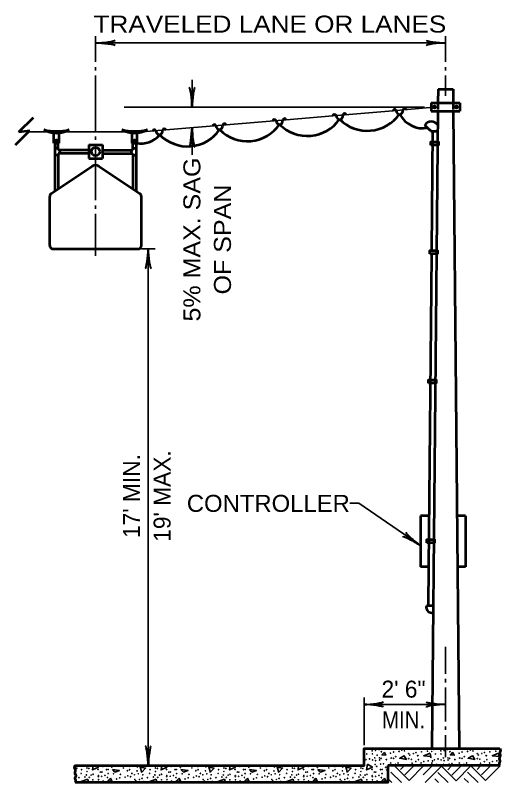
# Model space of a CAD drawing. Extents: x -1 to 679, y 1 to 441.
# Drawn here: x 376.2 to 447.7, y 250 to 362.8 of the extents above; entities that cross this region are included whole.
import ezdxf
from ezdxf.enums import TextEntityAlignment as Align

# ---------------------------------------------------------------- set-up
doc = ezdxf.new("R2010")
doc.units = 0
doc.layers.add('1', color=7, linetype='Continuous', lineweight=35)

msp = doc.modelspace()

# ---------------------------------------------------------------- hatches: boundary and pattern name
at = {"layer": '1'}
for points in [[(438.098, 349.333, 1), (437.774, 349.333, 1)], [(441.34, 349.333, 1), (441.016, 349.333, 1)], [(382.431, 344.383, 1), (382.181, 344.383, 1)], [(393.932, 344.38, 1), (393.682, 344.38, 1)]]:
    msp.add_hatch(color=256, dxfattribs=at).paths.add_polyline_path(points)

# ---------------------------------------------------------------- linework, layer by layer
for p, q in [((388.058, 359.754), (388.058, 355.955)), ((439.572, 355.955), (439.572, 359.754)), ((388.058, 358.754), (439.572, 358.754)), ((388.058, 355.205), (388.058, 354.705)), ((439.572, 354.705), (439.572, 355.205)), ((388.058, 353.955), (388.058, 345.754)), ((402.26, 349.33), (402.26, 353.33)), ((439.572, 350.955), (439.572, 353.955)), ((392.26, 349.33), (436.451, 349.33)), ((422.964, 348.038), (431.812, 348.784)), ((431.812, 348.784), (437.781, 349.287)), ((416.115, 347.461), (422.967, 348.038)), ((398.421, 345.969), (407.267, 346.715)), ((407.267, 346.715), (416.115, 347.461)), ((381.185, 345.675), (378.165, 345.675)), ((392.685, 345.675), (383.431, 345.675)), ((394.93, 345.675), (398.421, 345.969)), ((402.26, 342.293), (402.26, 346.293)), ((388.058, 345.004), (388.058, 344.504)), ((388.058, 340.754), (388.058, 335.605)), ((388.058, 334.855), (388.058, 334.355)), ((388.058, 333.605), (388.058, 328.456)), ((388.058, 328.456), (388.058, 327.456)), ((394.808, 328.456), (396.808, 328.456)), ((395.808, 328.456), (395.808, 252.456)), ((439.572, 265.956), (439.572, 269.956)), ((439.572, 264.706), (439.572, 265.206)), ((439.572, 258.956), (439.572, 263.956)), ((427.572, 255.456), (427.572, 262.456)), ((427.572, 261.456), (439.572, 261.456)), ((439.572, 257.706), (439.572, 258.206)), ((439.572, 256.956), (439.572, 253.706)), ((430.859, 251.872), (431.072, 251.848)), ((431.072, 251.66), (430.859, 251.872)), ((432.052, 252.416), (434.192, 250.276)), ((433.472, 252.416), (432.952, 251.896)), ((434.912, 252.416), (433.592, 251.096)), ((436.332, 252.416), (434.192, 250.276)), ((437.612, 252.416), (436.292, 251.096)), ((439.032, 252.416), (436.572, 249.956)), ((438.108, 252.456), (438.139, 252.672)), ((438.179, 252.652), (438.523, 252.456)), ((438.932, 252.416), (441.132, 250.216)), ((440.452, 252.416), (439.892, 251.836)), ((441.892, 252.416), (440.512, 251.036)), ((443.312, 252.416), (441.132, 250.216)), ((443.312, 252.416), (445.452, 250.276)), ((444.732, 252.416), (444.212, 251.896)), ((446.172, 252.416), (444.852, 251.096)), ((447.592, 252.416), (445.452, 250.276)), ((431.072, 250.556), (431.672, 249.956)), ((431.532, 251.516), (433.092, 249.956)), ((438.452, 251.456), (439.968, 249.956)), ((442.332, 250.556), (442.932, 249.956)), ((442.792, 251.516), (444.352, 249.956)), ((393.159, 250.112), (392.873, 249.956)), ((393.233, 249.956), (393.119, 250.132)), ((403.239, 250.112), (402.953, 249.956)), ((403.313, 249.956), (403.199, 250.132)), ((413.319, 250.112), (413.033, 249.956)), ((413.393, 249.956), (413.279, 250.132)), ((423.399, 250.112), (423.113, 249.956)), ((423.473, 249.956), (423.359, 250.132)), ((437.992, 250.496), (438.532, 249.956))]:
    msp.add_line(p, q, dxfattribs=at)
at = {"layer": '1', "lineweight": 53}
for p, q in [((438.47, 351.955), (438.451, 349.955)), ((438.47, 351.955), (440.673, 351.955)), ((440.673, 351.955), (440.692, 349.955)), ((437.451, 349.955), (441.692, 349.955)), ((437.451, 349.955), (437.451, 348.705)), ((441.692, 349.955), (441.692, 348.705)), ((438.449, 349.705), (438.442, 348.955)), ((440.694, 349.705), (440.701, 348.955)), ((376.783, 345.687), (378.905, 347.809)), ((437.451, 348.705), (441.692, 348.705)), ((438.44, 348.705), (437.572, 254.956)), ((440.704, 348.705), (441.572, 254.956)), ((437.222, 345.964), (436.515, 346.671)), ((376.25, 343.761), (378.372, 345.882)), ((376.783, 345.687), (378.372, 345.882)), ((381.933, 344.004), (381.933, 345.504)), ((382.683, 344.004), (382.683, 345.504)), ((393.433, 344.004), (393.433, 345.504)), ((394.183, 344.004), (394.183, 345.504)), ((438.412, 345.705), (437.412, 345.705)), ((437.662, 345.705), (437.5, 328.213)), ((381.933, 344.004), (382.683, 344.004)), ((382.058, 344.004), (382.058, 336.956)), ((382.558, 343.254), (382.058, 343.254)), ((382.558, 343.004), (382.558, 344.004)), ((387.058, 343.754), (389.058, 343.754)), ((387.058, 343.754), (387.058, 341.754)), ((389.058, 343.754), (389.058, 341.754)), ((393.433, 344.004), (394.183, 344.004)), ((393.558, 343.004), (393.558, 344.004)), ((393.558, 343.254), (394.058, 343.254)), ((394.058, 344.004), (394.058, 336.956)), ((382.558, 342.254), (382.058, 342.254)), ((387.058, 343.004), (382.558, 343.004)), ((387.058, 342.504), (382.558, 342.504)), ((382.558, 342.504), (382.558, 337.289)), ((382.808, 343.004), (382.808, 342.504)), ((389.058, 343.004), (393.558, 343.004)), ((389.058, 342.504), (393.558, 342.504)), ((393.308, 343.004), (393.308, 342.504)), ((393.558, 342.504), (393.558, 337.289)), ((393.558, 342.254), (394.058, 342.254)), ((387.058, 341.754), (389.058, 341.754)), ((381.53, 336.604), (387.503, 340.586)), ((388.612, 340.586), (394.585, 336.604)), ((381.308, 328.956), (381.308, 336.188)), ((394.808, 328.956), (394.808, 336.188)), ((381.808, 328.456), (394.308, 328.456)), ((437.495, 327.706), (437.069, 281.714)), ((435.889, 289.208), (435.889, 281.714)), ((437.139, 289.208), (435.889, 289.208)), ((442.504, 289.208), (441.255, 289.208)), ((442.504, 289.208), (442.504, 281.714)), ((437.069, 281.714), (435.889, 281.714)), ((437.069, 281.714), (437.016, 275.955)), ((442.504, 281.714), (441.324, 281.714)), ((437.766, 275.955), (436.766, 275.955)), ((447.572, 252.456), (431.072, 252.456))]:
    msp.add_line(p, q, dxfattribs=at)
at = {"layer": '1'}
for points in [[(388.058, 343.754), (388.058, 341.254), (388.058, 340.754)], [(435.881, 284.832), (426.821, 291.044), (425.49, 291.044)], [(430.579, 254.432), (430.199, 254.032), (430.779, 253.992), (430.579, 254.392)], [(433.479, 253.912), (432.819, 253.552), (433.799, 253.372), (433.439, 253.932)], [(437.299, 254.292), (436.359, 253.912), (437.399, 253.792), (437.299, 254.252)], [(440.659, 254.432), (440.279, 254.032), (440.859, 253.992), (440.659, 254.392)], [(443.559, 253.912), (442.899, 253.552), (443.879, 253.372), (443.519, 253.932)], [(447.379, 254.292), (446.439, 253.912), (447.479, 253.792), (447.379, 254.252)], [(384.961, 252.17), (385.339, 252.092), (385.089, 251.824)], [(388.123, 252.456), (388.479, 252.252), (387.619, 251.832), (387.708, 252.456)], [(394.879, 251.452), (394.639, 252.252), (395.419, 252.092), (394.859, 251.492)], [(398.203, 252.456), (398.559, 252.252), (397.699, 251.832), (397.788, 252.456)], [(404.959, 251.452), (404.719, 252.252), (405.499, 252.092), (404.939, 251.492)], [(408.283, 252.456), (408.639, 252.252), (407.779, 251.832), (407.868, 252.456)], [(415.039, 251.452), (414.799, 252.252), (415.579, 252.092), (415.019, 251.492)], [(418.363, 252.456), (418.719, 252.252), (417.859, 251.832), (417.948, 252.456)], [(425.119, 251.452), (424.879, 252.252), (425.659, 252.092), (425.099, 251.492)], [(428.099, 252.652), (428.799, 252.252), (427.939, 251.832), (428.059, 252.672)], [(390.259, 250.632), (389.879, 250.232), (390.459, 250.192), (390.259, 250.592)], [(400.339, 250.632), (399.959, 250.232), (400.539, 250.192), (400.339, 250.592)], [(410.419, 250.632), (410.039, 250.232), (410.619, 250.192), (410.419, 250.592)], [(420.499, 250.632), (420.119, 250.232), (420.699, 250.192), (420.499, 250.592)], [(430.579, 250.632), (430.199, 250.232), (430.779, 250.192), (430.579, 250.592)], [(386.899, 250.492), (385.959, 250.112), (386.999, 249.992), (386.899, 250.452)], [(396.979, 250.492), (396.039, 250.112), (397.079, 249.992), (396.979, 250.452)], [(407.059, 250.492), (406.119, 250.112), (407.159, 249.992), (407.059, 250.452)], [(417.139, 250.492), (416.199, 250.112), (417.239, 249.992), (417.139, 250.452)], [(427.219, 250.492), (426.279, 250.112), (427.319, 249.992), (427.219, 250.452)]]:
    msp.add_lwpolyline(points, dxfattribs=at)
at = {"layer": '1', "lineweight": 53}
for points in [[(437.412, 343.705), (437.412, 344.205), (438.537, 344.205), (438.537, 343.705)], [(437.268, 327.713), (437.268, 328.213), (438.393, 328.213), (438.393, 327.713)], [(437.077, 308.707), (437.077, 309.207), (438.202, 309.207), (438.202, 308.707)], [(436.835, 285.208), (436.835, 285.708), (437.96, 285.708), (437.96, 285.208)]]:
    msp.add_lwpolyline(points, close=True, dxfattribs=at)
for points in [[(385.072, 249.956), (385.163, 250.087), (385.168, 250.3), (385.059, 250.545), (385.075, 250.687), (385.19, 250.96), (385.064, 251.303), (385.037, 251.462), (385.092, 251.8), (385.075, 251.958), (384.961, 252.171), (385.072, 252.456), (427.572, 252.456), (427.572, 254.956), (447.572, 254.956)], [(447.572, 254.956), (447.683, 254.671), (447.568, 254.458), (447.552, 254.3), (447.606, 253.962), (447.579, 253.803), (447.453, 253.46), (447.568, 253.187), (447.584, 253.045), (447.475, 252.8), (447.481, 252.587), (447.572, 252.456)], [(431.072, 252.456), (431.072, 249.956), (385.072, 249.956)]]:
    msp.add_lwpolyline(points, dxfattribs=at)
at = {"layer": '1'}
for points in [[(390.539, 251.872), (391.579, 251.752), (390.899, 251.512)], [(400.619, 251.872), (401.659, 251.752), (400.979, 251.512)], [(410.699, 251.872), (411.739, 251.752), (411.059, 251.512)], [(420.779, 251.872), (421.819, 251.752), (421.139, 251.512)]]:
    msp.add_lwpolyline(points, close=True, dxfattribs=at)
at = {"layer": '1', "lineweight": 53}
for centre, radius in [((437.936, 349.333), 0.162), ((441.178, 349.333), 0.162), ((382.306, 344.383), 0.125), ((393.807, 344.38), 0.125), ((388.07, 342.764), 0.625)]:
    msp.add_circle(centre, radius, dxfattribs=at)
at = {"layer": '1'}
for centre in [(427.732, 254.869), (427.984, 254.171), (428.779, 254.635), (428.792, 254.803), (428.818, 254.184), (429.282, 254.688), (429.494, 253.999), (429.773, 254.816), (430.138, 254.503), (431.477, 254.29), (431.927, 254.463), (432.736, 254.556), (433.133, 254.75), (433.531, 254.622), (434.088, 254.909), (434.154, 254.224), (434.313, 254.012), (434.83, 254.224), (435.227, 254.383), (435.32, 254.909), (435.453, 253.919), (435.506, 253.919), (436.009, 254.489), (436.897, 254.582), (437.109, 254.895), (437.533, 254.542), (437.812, 254.869), (438.064, 254.171), (438.859, 254.635), (438.872, 254.803), (438.898, 254.184), (439.362, 254.688), (439.574, 253.999), (439.853, 254.816), (440.218, 254.503), (441.557, 254.29), (442.007, 254.463), (442.816, 254.556), (443.213, 254.75), (443.611, 254.622), (444.168, 254.909), (444.234, 254.224), (444.393, 254.012), (444.91, 254.224), (445.307, 254.383), (445.4, 254.909), (445.533, 253.919), (445.586, 253.919), (446.089, 254.489), (446.977, 254.582), (447.189, 254.895), (427.864, 253.323), (428.394, 253.442), (428.845, 253.296), (429.163, 253.588), (429.269, 253.19), (429.852, 253.601), (429.865, 253.283), (430.085, 253.522), (430.867, 253.349), (431.503, 252.845), (431.583, 253.575), (431.927, 253.535), (432.245, 253.773), (432.59, 252.845), (434.154, 253.482), (434.538, 253.389), (434.657, 252.819), (435.201, 253.058), (435.572, 253.336), (435.97, 252.845), (436.38, 253.071), (437.03, 253.164), (437.427, 253.654), (437.56, 252.832), (437.666, 253.15), (437.944, 253.323), (438.474, 253.442), (438.925, 253.296), (439.243, 253.588), (439.349, 253.19), (439.932, 253.601), (439.945, 253.283), (440.165, 253.522), (440.947, 253.349), (441.583, 252.845), (441.663, 253.575), (442.007, 253.535), (442.325, 253.773), (442.67, 252.845), (444.234, 253.482), (444.618, 253.389), (444.737, 252.819), (445.281, 253.058), (445.652, 253.336), (446.05, 252.845), (446.46, 253.071), (447.11, 253.164), (386.007, 251.864), (386.789, 252.116), (387.08, 252.05), (388.432, 251.904), (389.121, 252.342), (389.685, 251.875), (389.911, 251.891), (390.454, 252.222), (392.151, 252.116), (392.747, 251.705), (393.025, 252.342), (393.065, 251.851), (394.165, 251.679), (394.205, 252.275), (396.087, 251.864), (396.869, 252.116), (397.16, 252.05), (398.512, 251.904), (399.201, 252.342), (399.765, 251.875), (399.991, 251.891), (400.534, 252.222), (402.231, 252.116), (402.827, 251.705), (403.105, 252.342), (403.145, 251.851), (404.245, 251.679), (404.285, 252.275), (406.167, 251.864), (406.949, 252.116), (407.24, 252.05), (408.592, 251.904), (409.281, 252.342), (409.845, 251.875), (410.071, 251.891), (410.614, 252.222), (412.311, 252.116), (412.907, 251.705), (413.185, 252.342), (413.225, 251.851), (414.325, 251.679), (414.365, 252.275), (416.247, 251.864), (417.029, 252.116), (417.32, 252.05), (418.672, 251.904), (419.361, 252.342), (419.925, 251.875), (420.151, 251.891), (420.694, 252.222), (422.391, 252.116), (422.987, 251.705), (423.265, 252.342), (423.305, 251.851), (424.405, 251.679), (424.445, 252.275), (426.327, 251.864), (427.109, 252.116), (427.4, 252.05), (428.752, 251.904), (429.216, 252.633), (429.441, 252.342), (430.005, 251.875), (430.025, 252.686), (430.231, 251.891), (430.443, 252.739), (430.774, 252.222), (432.192, 252.633), (433.756, 252.514), (437.494, 252.527), (439.296, 252.633), (440.105, 252.686), (440.523, 252.739), (442.272, 252.633), (443.836, 252.514), (385.609, 250.689), (385.941, 251.321), (386.497, 250.782), (386.709, 251.095), (386.802, 251.599), (387.133, 250.742), (387.412, 251.069), (387.69, 251.188), (388.459, 250.835), (388.472, 251.003), (388.764, 251.506), (388.962, 250.888), (388.989, 251.506), (389.453, 251.016), (389.818, 250.703), (389.911, 251.294), (390.719, 251.255), (391.607, 250.663), (391.713, 251.175), (392.416, 250.756), (392.813, 250.95), (393.211, 250.822), (393.41, 251.308), (393.768, 251.109), (394.351, 251.255), (394.907, 250.583), (395, 251.109), (395.689, 250.689), (396.021, 251.321), (396.577, 250.782), (396.789, 251.095), (396.882, 251.599), (397.213, 250.742), (397.492, 251.069), (397.77, 251.188), (398.539, 250.835), (398.552, 251.003), (398.844, 251.506), (399.042, 250.888), (399.069, 251.506), (399.533, 251.016), (399.898, 250.703), (399.991, 251.294), (400.799, 251.255), (401.687, 250.663), (401.793, 251.175), (402.496, 250.756), (402.893, 250.95), (403.291, 250.822), (403.49, 251.308), (403.848, 251.109), (404.431, 251.255), (404.987, 250.583), (405.08, 251.109), (405.769, 250.689), (406.101, 251.321), (406.657, 250.782), (406.869, 251.095), (406.962, 251.599), (407.293, 250.742), (407.572, 251.069), (407.85, 251.188), (408.619, 250.835), (408.632, 251.003), (408.924, 251.506), (409.122, 250.888), (409.149, 251.506), (409.613, 251.016), (409.978, 250.703), (410.071, 251.294), (410.879, 251.255), (411.767, 250.663), (411.873, 251.175), (412.576, 250.756), (412.973, 250.95), (413.371, 250.822), (413.57, 251.308), (413.928, 251.109), (414.511, 251.255), (415.067, 250.583), (415.16, 251.109), (415.849, 250.689), (416.181, 251.321), (416.737, 250.782), (416.949, 251.095), (417.042, 251.599), (417.373, 250.742), (417.652, 251.069), (417.93, 251.188), (418.699, 250.835), (418.712, 251.003), (419.004, 251.506), (419.202, 250.888), (419.229, 251.506), (419.693, 251.016), (420.058, 250.703), (420.151, 251.294), (420.959, 251.255), (421.847, 250.663), (421.953, 251.175), (422.656, 250.756), (423.053, 250.95), (423.451, 250.822), (423.65, 251.308), (424.008, 251.109), (424.591, 251.255), (425.147, 250.583), (425.24, 251.109), (425.929, 250.689), (426.261, 251.321), (426.817, 250.782), (427.029, 251.095), (427.122, 251.599), (427.453, 250.742), (427.732, 251.069), (428.01, 251.188), (428.779, 250.835), (428.792, 251.003), (429.084, 251.506), (429.282, 250.888), (429.309, 251.506), (429.773, 251.016), (430.138, 250.703), (430.231, 251.294), (431.039, 251.255), (387.664, 250.371), (388.498, 250.384), (389.174, 250.199), (391.157, 250.49), (393.834, 250.424), (393.993, 250.212), (394.51, 250.424), (395.133, 250.119), (395.186, 250.119), (397.744, 250.371), (398.578, 250.384), (399.254, 250.199), (401.237, 250.49), (403.914, 250.424), (404.073, 250.212), (404.59, 250.424), (405.213, 250.119), (405.266, 250.119), (407.824, 250.371), (408.658, 250.384), (409.334, 250.199), (411.317, 250.49), (413.994, 250.424), (414.153, 250.212), (414.67, 250.424), (415.293, 250.119), (415.346, 250.119), (417.904, 250.371), (418.738, 250.384), (419.414, 250.199), (421.397, 250.49), (424.074, 250.424), (424.233, 250.212), (424.75, 250.424), (425.373, 250.119), (425.426, 250.119), (427.984, 250.371), (428.818, 250.384), (429.494, 250.199)]:
    msp.add_circle(centre, 0.0265, dxfattribs=at)
at = {"layer": '1', "lineweight": 53}
for centre, radius, start, end in [((432.069, 348.712), 0.267, 25.5313, 164.45861), ((433.563, 348.843), 0.267, 24.08975, 164.4687), ((415.871, 347.352), 0.267, 24.08975, 164.4687), ((423.222, 347.966), 0.267, 25.5313, 164.45861), ((428.051, 351.596), 5.764, 224.78783, 325.11132), ((424.716, 348.097), 0.267, 24.08975, 164.4687), ((436.223, 349.995), 3.789, 207.50003, 280.53329), ((405.529, 346.475), 0.267, 25.5313, 164.45861), ((410.413, 350.069), 5.764, 224.78783, 325.11132), ((407.023, 346.606), 0.267, 24.08975, 164.4687), ((414.377, 347.221), 0.267, 25.5313, 164.45861), ((419.232, 350.832), 5.764, 224.78783, 325.11132), ((437.478, 346.077), 1.131, 32.91213, 148.34152), ((382.308, 349.27), 3.766, 240.13717, 299.86284), ((382.308, 352.91), 7.156, 254.81071, 285.18929), ((393.808, 349.27), 3.766, 240.13717, 299.86284), ((393.808, 352.91), 7.156, 254.81071, 285.18929), ((396.683, 345.73), 0.267, 25.5313, 164.45861), ((401.594, 349.305), 5.764, 224.78783, 325.11132), ((398.177, 345.86), 0.267, 24.08975, 164.4687), ((437.213, 345.758), 0.205, 344.97633, 87.57779), ((394.668, 347.716), 3.762, 260.66909, 318.91993), ((388.058, 339.754), 1, 56.30808, 123.69007), ((381.808, 336.188), 0.5, 123.69239, 180), ((394.308, 336.188), 0.5, 0, 56.30661), ((381.808, 328.956), 0.5, 180, 270), ((394.308, 328.956), 0.5, 270, 0), ((437.562, 275.753), 0.821, 165.76102, 283.71131)]:
    msp.add_arc(centre, radius, start, end, dxfattribs=at)
at = {"layer": '1'}
for centre, start, end in [((432.033, 254.975), 226.35082, 313.64918), ((442.113, 254.975), 226.35082, 313.64918), ((447.613, 254.542), 61.61934, 241.7845), ((427.586, 253.15), 237.37076, 122.62924), ((447.507, 253.654), 32.83014, 287.06312), ((385.848, 252.474), 223.9797, 316.0203), ((386.365, 252.448), 162.01481, 17.98519), ((391.13, 252.448), 162.01481, 17.98519), ((395.928, 252.474), 223.9797, 316.0203), ((396.445, 252.448), 162.01481, 17.98519), ((401.21, 252.448), 162.01481, 17.98519), ((406.008, 252.474), 223.9797, 316.0203), ((406.525, 252.448), 162.01481, 17.98519), ((411.29, 252.448), 162.01481, 17.98519), ((416.088, 252.474), 223.9797, 316.0203), ((416.605, 252.448), 162.01481, 17.98519), ((421.37, 252.448), 162.01481, 17.98519), ((426.168, 252.474), 223.9797, 316.0203), ((426.685, 252.448), 162.01481, 17.98519), ((431.45, 252.448), 17.98519, 162.01481), ((436.248, 252.474), 316.0203, 223.9797), ((436.765, 252.448), 17.98519, 162.01481), ((441.53, 252.448), 17.98519, 162.01481), ((446.328, 252.474), 316.0203, 223.9797), ((446.845, 252.448), 17.98519, 162.01481), ((391.925, 249.973), 318.30023, 221.69977), ((402.005, 249.973), 318.30023, 221.69977), ((412.085, 249.973), 318.30023, 221.69977), ((422.165, 249.973), 318.30023, 221.69977)]:
    msp.add_arc(centre, 0.0265, start, end, dxfattribs=at)
at = {"layer": '1', "lineweight": 40}
for centre, major_axis, ratio, start_param, end_param in [((389.149, 359.03), (-1.786, -0.156), 0.122415, 0.8963533, 3.1415927), ((438.451, 358.966), (1.756, -0.176), 0.07063, 3.1407148, 5.41811), ((389.178, 358.542), (-1.756, 0.176), 0.07063, 3.1407148, 5.41811), ((438.48, 358.478), (1.786, 0.156), 0.122415, 0.8963533, 3.1415927), ((401.984, 350.421), (0.156, -1.786), 0.122415, 0.8963533, 3.1415927), ((401.984, 350.421), (0.156, -1.786), 0.122415, 0.8963533, 3.1415927), ((402.472, 350.451), (-0.176, -1.756), 0.07063, 3.1407148, 5.41811), ((402.472, 350.451), (-0.176, -1.756), 0.07063, 3.1407148, 5.41811), ((402.049, 345.173), (0.176, 1.756), 0.07063, 3.1407148, 5.41811), ((402.049, 345.173), (0.176, 1.756), 0.07063, 3.1407148, 5.41811), ((402.537, 345.202), (-0.156, 1.786), 0.122415, 0.8963533, 3.1415927), ((402.537, 345.202), (-0.156, 1.786), 0.122415, 0.8963533, 3.1415927), ((395.596, 327.335), (0.176, 1.756), 0.07063, 3.1407148, 5.41811), ((396.084, 327.365), (-0.156, 1.786), 0.122415, 0.8963533, 3.1415927), ((435.125, 285.675), (1.384, -1.139), 0.122415, 3.1415927, 5.386832), ((434.825, 285.289), (-1.548, 0.848), 0.07063, 4.006668, 6.2840632), ((428.663, 261.732), (-1.786, -0.156), 0.122415, 0.8963533, 3.1415927), ((428.663, 261.732), (-1.786, -0.156), 0.122415, 0.8963533, 3.1415927), ((438.451, 261.667), (1.756, -0.176), 0.07063, 3.1407148, 5.41811), ((428.692, 261.244), (-1.756, 0.176), 0.07063, 3.1407148, 5.41811), ((428.692, 261.244), (-1.756, 0.176), 0.07063, 3.1407148, 5.41811), ((438.48, 261.18), (1.786, 0.156), 0.122415, 0.8963533, 3.1415927), ((395.531, 253.547), (0.156, -1.786), 0.122415, 0.8963533, 3.1415927), ((396.019, 253.576), (-0.176, -1.756), 0.07063, 3.1407148, 5.41811)]:
    msp.add_ellipse(centre, major_axis=major_axis, ratio=ratio, start_param=start_param, end_param=end_param, dxfattribs=at)
at = {"layer": '1', "lineweight": 53}
for centre in [(432.808, 348.871), (423.961, 348.125), (406.268, 346.634), (415.116, 347.38), (397.422, 345.888)]:
    msp.add_ellipse(centre, major_axis=(0.055, -0.626), ratio=0.795507, start_param=4.712389, end_param=7.8539816, dxfattribs=at)

# ---------------------------------------------------------------- texts
at = {"layer": '1'}
for s, width, p in [('TRAVELED LANE OR LANES', 1.15, (413.719, 360.276)), ('MIN.', 0.9, (433.386, 257.96))]:
    msp.add_text(s, height=2.5, dxfattribs=dict(at, width=width)).set_placement(p, align=Align.CENTER)
at = {"layer": '1', "width": 1.1}
for s, p in [('5% MAX. SAG', (403.486, 329.836)), ('OF SPAN', (407.986, 329.836))]:
    msp.add_text(s, height=2.5, rotation=90, dxfattribs=at).set_placement(p, align=Align.CENTER)
at = {"layer": '1'}
for s, p in [("17' MIN.", (394.598, 292.114)), ("19' MAX.", (399.098, 292.114))]:
    msp.add_text(s, height=2.5, rotation=90, dxfattribs=at).set_placement(p, align=Align.CENTER)
at = {"layer": '1', "width": 1.05}
msp.add_text('CONTROLLER', height=2.5, dxfattribs=at).set_placement((401.49, 289.786))
at = {"layer": '1'}
msp.add_text('2\' 6"', height=2.5, dxfattribs=at).set_placement((433.387, 262.46), align=Align.CENTER)

doc.saveas('drawing.dxf')
